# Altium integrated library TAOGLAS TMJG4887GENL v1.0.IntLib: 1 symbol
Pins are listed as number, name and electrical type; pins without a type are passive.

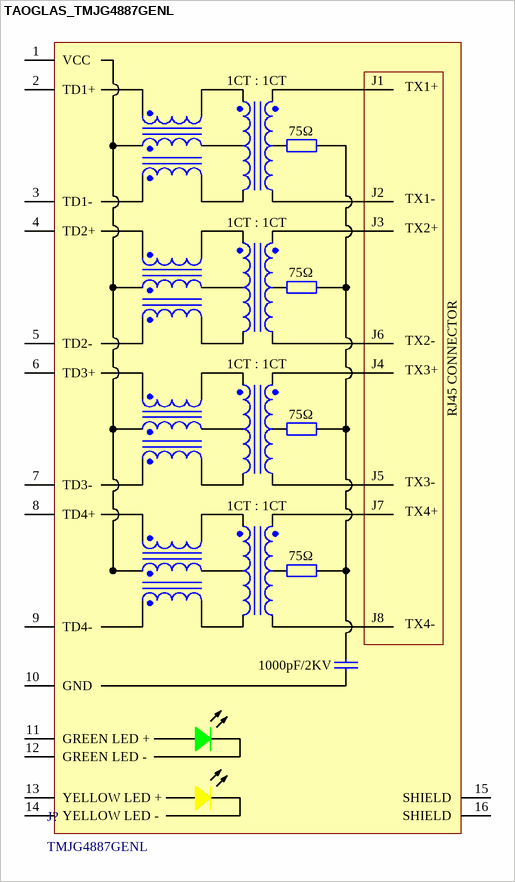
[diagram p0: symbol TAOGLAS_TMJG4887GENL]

## TAOGLAS_TMJG4887GENL
designator J?, comment TMJG4887GENL
RJ45 connector with integrated magnetics 1G Base-T. Single Port Tab-DOWN with right angle THT mount and LEDs.; ComponentLibStatus: Created; MFG: Taoglas; Temp_High: +85C; Temp_Low: -40C
footprint TAOGLAS_TMJG4887GENL (RJ45 connector with integrated magnetics 1G Base-T. Single Port Tab-DOWN with right angle THT mount and LEDs.)
pins: 1 VCC, 2 TD1+, 3 TD1-, 4 TD2+, 5 TD2-, 6 TD3+, 7 TD3-, 8 TD4+, 9 TD4-, 10 GND, 11 GREEN LED +, 12 GREEN LED -, 13 YELLOW LED +, 14 YELLOW LED -, 15 SHIELD, 16 SHIELD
